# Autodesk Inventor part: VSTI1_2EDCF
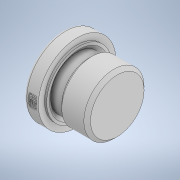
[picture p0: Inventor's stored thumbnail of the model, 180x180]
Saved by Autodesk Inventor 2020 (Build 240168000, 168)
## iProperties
Created: 2019-12
Part Number: VSTI1_2EDCF
Material: Generico
Description: STEP AP203
Document SubType Name: Modeling
Designer: carlo
Density: 1 g/cm^3
Appearance: Default
DataBaseUnit: MM
Title: p:/temp/worker_129/temp/exporttempdir_5904_804_40hyd/format_0/EO Verschluss-Stopfen fuer Einschraubloecher VSTI1_2EDCF.stp
Revision Number: NONE
Sending System: PARTsolutions
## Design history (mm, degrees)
feature "_EO Verschluss-Stopfen fuer Einschraubloecher VSTI1_2EDCF"
node "Piano di lavoro1"
node "Piano di lavoro2"
node "Asse di lavoro1"
node "Solido1"
other parameters: "d0" = 0, "d1" = 0
